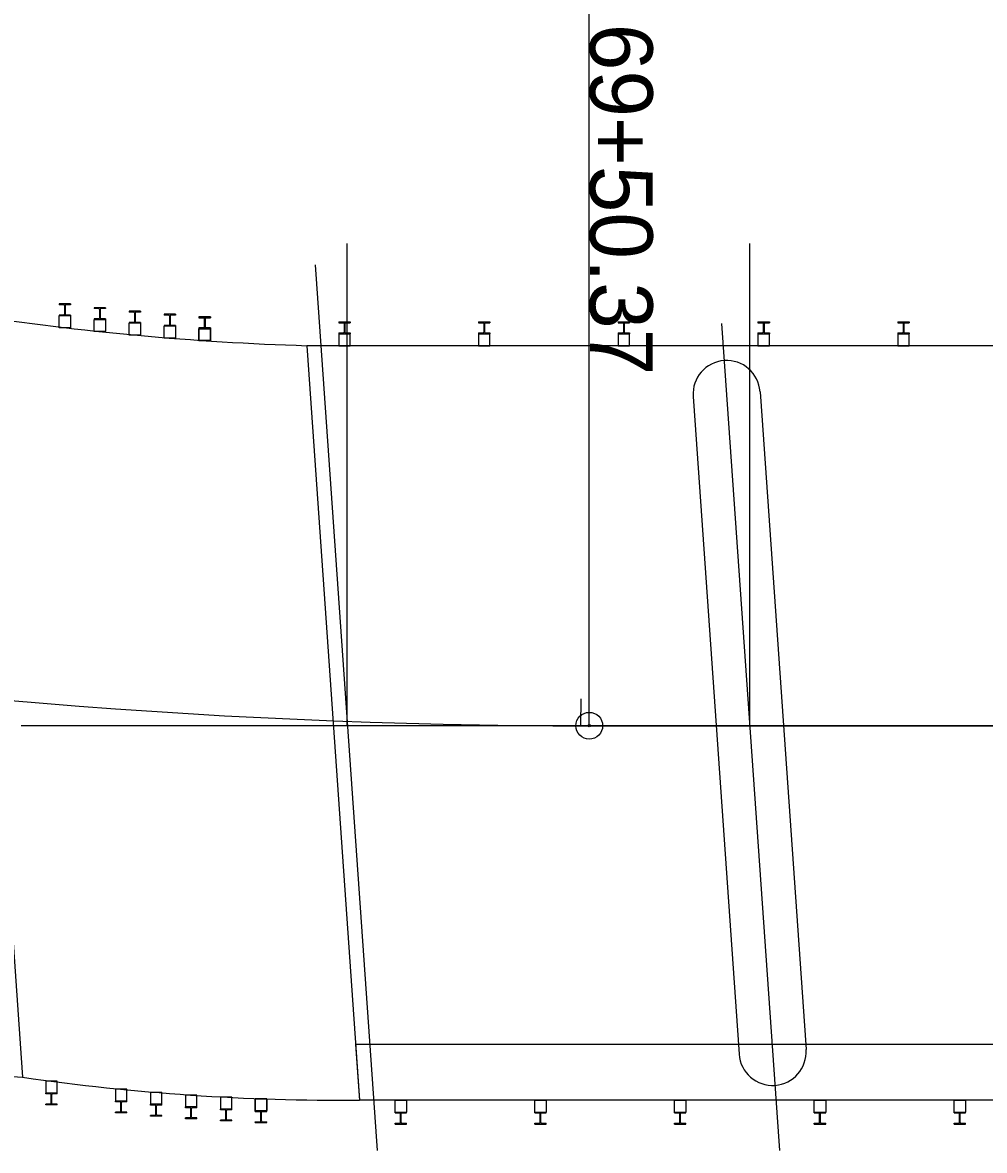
# Model space of a CAD drawing. Extents: x 27625 to 127752, y 6088 to 302357.
# Drawn here: x 27832.4 to 27875.5, y 6087.7 to 6138.1 of the extents above; entities that cross this region are included whole.
import ezdxf

# ---------------------------------------------------------------- set-up
doc = ezdxf.new("R2010")
doc.units = 0
for name, color, linetype in [('_CIVIL_CONSTRUCTION', 7, 'Continuous'), ('DR_X_Cells', 7, 'Continuous'), ('DV_X_Property_Line', 7, 'Continuous'), ('DV_X_Section_VMS_Line', 7, 'Continuous'), ('RS_Raster1', 7, 'Continuous'), ('RW_X_CL', 7, 'Continuous'), ('RW_X_CL_100_Bearings', 7, 'Continuous'), ('RW_X_CL_100_Cardinal_Points', 7, 'Continuous'), ('RW_X_CL_100_Curve_Data', 7, 'Continuous'), ('RW_X_CL_100_Stations', 7, 'Continuous'), ('RW_X_Fee_RW', 7, 'Continuous'), ('SC_Scratch2', 7, 'Continuous'), ('SV_X_Mon_Cells_Found', 7, 'Continuous'), ('SV_X_Shot_Marker', 7, 'Continuous'), ('TopoDOT_Transients', 7, 'Continuous')]:
    doc.layers.add(name, color=color, linetype=linetype)

msp = doc.modelspace()

# ---------------------------------------------------------------- linework, layer by layer
at = {"layer": '_CIVIL_CONSTRUCTION'}
for p, q in [((27846.96, 6106.658), (27846.96, 6128.23)), ((27864.96, 6106.658), (27864.96, 6128.23))]:
    msp.add_line(p, q, dxfattribs=at)
at = {"layer": 'DR_X_Cells'}
msp.add_line((27857.411, 6106.658), (27857.412, 6107.858), dxfattribs=at)
msp.add_line((27857.411, 6106.658), (27857.412, 6107.858), dxfattribs=at)
at = {"layer": 'DV_X_Property_Line'}
for p, q in [((27904.895, 6123.658), (27845.148, 6123.658)), ((27907.255, 6089.908), (27847.508, 6089.908))]:
    msp.add_line(p, q, dxfattribs=at)
at = {"layer": 'DV_X_Section_VMS_Line'}
msp.add_line((27905.46, 6106.658), (27832.372, 6106.658), dxfattribs=at)
at = {"layer": 'RS_Raster1'}
msp.add_circle((27857.78, 6106.658), 0.05, dxfattribs=at)
msp.add_circle((27857.78, 6106.658), 0.05, dxfattribs=at)
at = {"layer": 'RW_X_CL'}
for p, q in [((27862.426, 6121.39), (27864.484, 6091.966)), ((27865.419, 6121.6), (27867.477, 6092.176))]:
    msp.add_line(p, q, dxfattribs=at)
for centre, start, end in [((27863.923, 6121.495), 4, 184), ((27865.98, 6092.071), 184, 4)]:
    msp.add_arc(centre, 1.5, start, end, dxfattribs=at)
at = {"layer": 'RW_X_CL_100_Bearings'}
for p, q in [((27830.051, 6125.043), (27832.436, 6090.939)), ((27845.148, 6123.658), (27847.508, 6089.908))]:
    msp.add_line(p, q, dxfattribs=at)
for centre, radius, start, end in [((27849.042, 6249.077), 125.479, 261.29504, 268.22168), ((27846.864, 6191.18), 101.274, 261.80938, 270.36429)]:
    msp.add_arc(centre, radius, start, end, dxfattribs=at)
at = {"layer": 'RW_X_CL_100_Cardinal_Points'}
msp.add_line((27834.331, 6125.451), (27834.331, 6125.451), dxfattribs=at)
msp.add_arc((27857.78, 6401.934), 312.026, 262.69406, 265.34103, dxfattribs=at)
at = {"layer": 'RW_X_CL_100_Curve_Data'}
for p, q in [((27834.586, 6125.525), (27834.075, 6125.525)), ((27834.075, 6125.525), (27834.075, 6125.489)), ((27834.284, 6125.489), (27834.075, 6125.489)), ((27834.315, 6125.458), (27834.315, 6125.062)), ((27834.346, 6125.458), (27834.346, 6125.062)), ((27834.586, 6125.489), (27834.377, 6125.489)), ((27834.586, 6125.525), (27834.586, 6125.489)), ((27836.148, 6125.351), (27835.638, 6125.351)), ((27835.638, 6125.351), (27835.638, 6125.314)), ((27835.846, 6125.314), (27835.638, 6125.314)), ((27835.877, 6125.283), (27835.877, 6124.887)), ((27835.909, 6125.283), (27835.909, 6124.887)), ((27836.148, 6125.314), (27835.94, 6125.314)), ((27836.148, 6125.351), (27836.148, 6125.314)), ((27837.711, 6125.196), (27837.2, 6125.196)), ((27837.2, 6125.196), (27837.2, 6125.16)), ((27837.711, 6125.196), (27837.711, 6125.16)), ((27834.075, 6125.03), (27834.075, 6124.994)), ((27834.284, 6125.03), (27834.075, 6125.03)), ((27834.586, 6124.994), (27834.075, 6124.994)), ((27834.075, 6124.463), (27834.075, 6124.994)), ((27834.586, 6125.03), (27834.377, 6125.03)), ((27834.586, 6125.03), (27834.586, 6124.994)), ((27834.586, 6124.994), (27834.586, 6124.463)), ((27835.638, 6124.856), (27835.638, 6124.82)), ((27835.846, 6124.856), (27835.638, 6124.856)), ((27836.148, 6124.82), (27835.638, 6124.82)), ((27835.638, 6124.288), (27835.638, 6124.82)), ((27836.148, 6124.856), (27835.94, 6124.856)), ((27836.148, 6124.856), (27836.148, 6124.82)), ((27836.148, 6124.82), (27836.148, 6124.288)), ((27837.409, 6125.16), (27837.2, 6125.16)), ((27837.2, 6124.701), (27837.2, 6124.665)), ((27837.409, 6124.701), (27837.2, 6124.701)), ((27837.44, 6125.128), (27837.44, 6124.732)), ((27837.471, 6125.128), (27837.471, 6124.732)), ((27837.711, 6125.16), (27837.502, 6125.16)), ((27837.711, 6124.701), (27837.502, 6124.701)), ((27837.711, 6124.701), (27837.711, 6124.665)), ((27839.273, 6125.061), (27838.763, 6125.061)), ((27838.763, 6125.061), (27838.763, 6125.024)), ((27838.971, 6125.024), (27838.763, 6125.024)), ((27839.002, 6124.993), (27839.002, 6124.597)), ((27839.034, 6124.993), (27839.034, 6124.597)), ((27839.273, 6125.024), (27839.065, 6125.024)), ((27839.273, 6125.061), (27839.273, 6125.024)), ((27840.325, 6124.945), (27840.836, 6124.945)), ((27840.325, 6124.945), (27840.325, 6124.909)), ((27840.836, 6124.945), (27840.325, 6124.945)), ((27840.325, 6124.945), (27840.325, 6124.909)), ((27840.325, 6124.909), (27840.534, 6124.909)), ((27840.534, 6124.909), (27840.325, 6124.909)), ((27840.565, 6124.878), (27840.565, 6124.482)), ((27840.565, 6124.878), (27840.565, 6124.482)), ((27840.596, 6124.878), (27840.596, 6124.482)), ((27840.596, 6124.878), (27840.596, 6124.482)), ((27840.627, 6124.909), (27840.836, 6124.909)), ((27840.836, 6124.909), (27840.627, 6124.909)), ((27840.836, 6124.945), (27840.836, 6124.909)), ((27840.836, 6124.945), (27840.836, 6124.909)), ((27846.575, 6124.72), (27847.086, 6124.72)), ((27846.575, 6124.72), (27846.575, 6124.684)), ((27846.575, 6124.684), (27846.784, 6124.684)), ((27846.877, 6124.684), (27847.086, 6124.684)), ((27847.086, 6124.72), (27847.086, 6124.684)), ((27852.825, 6124.72), (27853.336, 6124.72)), ((27852.825, 6124.72), (27852.825, 6124.684)), ((27852.825, 6124.684), (27853.034, 6124.684)), ((27853.127, 6124.684), (27853.336, 6124.684)), ((27853.336, 6124.72), (27853.336, 6124.684)), ((27859.075, 6124.72), (27859.586, 6124.72)), ((27859.075, 6124.72), (27859.075, 6124.684)), ((27859.075, 6124.684), (27859.284, 6124.684)), ((27859.377, 6124.684), (27859.586, 6124.684)), ((27859.586, 6124.72), (27859.586, 6124.684)), ((27865.325, 6124.72), (27865.836, 6124.72)), ((27865.325, 6124.72), (27865.325, 6124.684)), ((27865.325, 6124.684), (27865.534, 6124.684)), ((27865.627, 6124.684), (27865.836, 6124.684)), ((27865.836, 6124.72), (27865.836, 6124.684)), ((27871.575, 6124.72), (27872.086, 6124.72)), ((27871.575, 6124.72), (27871.575, 6124.684)), ((27871.575, 6124.684), (27871.784, 6124.684)), ((27871.877, 6124.684), (27872.086, 6124.684)), ((27872.086, 6124.72), (27872.086, 6124.684)), ((27837.711, 6124.665), (27837.2, 6124.665)), ((27837.2, 6124.134), (27837.2, 6124.665)), ((27837.711, 6124.665), (27837.711, 6124.134)), ((27838.763, 6124.566), (27838.763, 6124.53)), ((27838.971, 6124.566), (27838.763, 6124.566)), ((27839.273, 6124.53), (27838.763, 6124.53)), ((27838.763, 6123.999), (27838.763, 6124.53)), ((27839.273, 6124.566), (27839.065, 6124.566)), ((27839.273, 6124.566), (27839.273, 6124.53)), ((27839.273, 6124.53), (27839.273, 6123.999)), ((27840.325, 6124.451), (27840.325, 6124.414)), ((27840.325, 6124.451), (27840.534, 6124.451)), ((27840.325, 6124.451), (27840.325, 6124.414)), ((27840.534, 6124.451), (27840.325, 6124.451)), ((27840.325, 6124.414), (27840.836, 6124.414)), ((27840.325, 6124.414), (27840.325, 6123.883)), ((27840.836, 6124.414), (27840.325, 6124.414)), ((27840.325, 6123.883), (27840.325, 6124.414)), ((27840.627, 6124.451), (27840.836, 6124.451)), ((27840.836, 6124.451), (27840.627, 6124.451)), ((27840.836, 6124.451), (27840.836, 6124.414)), ((27840.836, 6124.451), (27840.836, 6124.414)), ((27840.836, 6123.883), (27840.836, 6124.414)), ((27840.836, 6124.414), (27840.836, 6123.883)), ((27846.575, 6124.226), (27846.575, 6124.189)), ((27846.575, 6124.226), (27846.784, 6124.226)), ((27846.575, 6124.189), (27847.086, 6124.189)), ((27846.575, 6124.189), (27846.575, 6123.658)), ((27846.815, 6124.653), (27846.815, 6124.257)), ((27846.846, 6124.653), (27846.846, 6124.257)), ((27846.877, 6124.226), (27847.086, 6124.226)), ((27847.086, 6124.226), (27847.086, 6124.189)), ((27847.086, 6123.658), (27847.086, 6124.189)), ((27852.825, 6124.226), (27852.825, 6124.189)), ((27852.825, 6124.226), (27853.034, 6124.226)), ((27852.825, 6124.189), (27853.336, 6124.189)), ((27852.825, 6124.189), (27852.825, 6123.658)), ((27853.065, 6124.653), (27853.065, 6124.257)), ((27853.096, 6124.653), (27853.096, 6124.257)), ((27853.127, 6124.226), (27853.336, 6124.226)), ((27853.336, 6124.226), (27853.336, 6124.189)), ((27853.336, 6123.658), (27853.336, 6124.189)), ((27859.075, 6124.226), (27859.075, 6124.189)), ((27859.075, 6124.226), (27859.284, 6124.226)), ((27859.075, 6124.189), (27859.586, 6124.189)), ((27859.075, 6124.189), (27859.075, 6123.658)), ((27859.315, 6124.653), (27859.315, 6124.257)), ((27859.346, 6124.653), (27859.346, 6124.257)), ((27859.377, 6124.226), (27859.586, 6124.226)), ((27859.586, 6124.226), (27859.586, 6124.189)), ((27859.586, 6123.658), (27859.586, 6124.189)), ((27865.325, 6124.226), (27865.325, 6124.189)), ((27865.325, 6124.226), (27865.534, 6124.226)), ((27865.325, 6124.189), (27865.836, 6124.189)), ((27865.325, 6124.189), (27865.325, 6123.658)), ((27865.565, 6124.653), (27865.565, 6124.257)), ((27865.596, 6124.653), (27865.596, 6124.257)), ((27865.627, 6124.226), (27865.836, 6124.226)), ((27865.836, 6124.226), (27865.836, 6124.189)), ((27865.836, 6123.658), (27865.836, 6124.189)), ((27871.575, 6124.226), (27871.575, 6124.189)), ((27871.575, 6124.226), (27871.784, 6124.226)), ((27871.575, 6124.189), (27872.086, 6124.189)), ((27871.575, 6124.189), (27871.575, 6123.658)), ((27871.815, 6124.653), (27871.815, 6124.257)), ((27871.846, 6124.653), (27871.846, 6124.257)), ((27871.877, 6124.226), (27872.086, 6124.226)), ((27872.086, 6124.226), (27872.086, 6124.189)), ((27872.086, 6123.658), (27872.086, 6124.189)), ((27833.47, 6090.762), (27833.47, 6090.231)), ((27833.981, 6090.231), (27833.981, 6090.762)), ((27836.595, 6090.402), (27836.595, 6089.871)), ((27837.106, 6089.871), (27837.106, 6090.402)), ((27833.981, 6090.231), (27833.47, 6090.231)), ((27833.47, 6090.194), (27833.47, 6090.231)), ((27833.679, 6090.194), (27833.47, 6090.194)), ((27833.71, 6089.767), (27833.71, 6090.163)), ((27833.741, 6089.767), (27833.741, 6090.163)), ((27833.981, 6090.194), (27833.772, 6090.194)), ((27833.981, 6090.194), (27833.981, 6090.231)), ((27837.106, 6089.871), (27836.595, 6089.871)), ((27836.595, 6089.835), (27836.595, 6089.871)), ((27837.106, 6089.835), (27837.106, 6089.871)), ((27838.158, 6090.259), (27838.158, 6089.728)), ((27838.668, 6089.728), (27838.668, 6090.259)), ((27839.72, 6090.14), (27839.72, 6089.609)), ((27840.231, 6089.609), (27840.231, 6090.14)), ((27841.283, 6090.046), (27841.283, 6089.515)), ((27841.793, 6089.515), (27841.793, 6090.046)), ((27842.845, 6089.445), (27842.845, 6089.976)), ((27842.845, 6089.976), (27842.845, 6089.445)), ((27843.356, 6089.976), (27843.356, 6089.445)), ((27843.356, 6089.445), (27843.356, 6089.976)), ((27849.095, 6089.377), (27849.095, 6089.908)), ((27849.606, 6089.908), (27849.606, 6089.377)), ((27855.345, 6089.377), (27855.345, 6089.908)), ((27855.856, 6089.908), (27855.856, 6089.377)), ((27861.595, 6089.377), (27861.595, 6089.908)), ((27862.106, 6089.908), (27862.106, 6089.377)), ((27867.845, 6089.377), (27867.845, 6089.908)), ((27868.356, 6089.908), (27868.356, 6089.377)), ((27874.095, 6089.377), (27874.095, 6089.908)), ((27874.606, 6089.908), (27874.606, 6089.377)), ((27833.47, 6089.699), (27833.47, 6089.736)), ((27833.679, 6089.736), (27833.47, 6089.736)), ((27833.981, 6089.699), (27833.47, 6089.699)), ((27833.981, 6089.736), (27833.772, 6089.736)), ((27833.981, 6089.699), (27833.981, 6089.736)), ((27836.804, 6089.835), (27836.595, 6089.835)), ((27836.595, 6089.34), (27836.595, 6089.376)), ((27836.804, 6089.376), (27836.595, 6089.376)), ((27836.835, 6089.407), (27836.835, 6089.803)), ((27836.866, 6089.407), (27836.866, 6089.803)), ((27837.106, 6089.835), (27836.897, 6089.835)), ((27837.106, 6089.376), (27836.897, 6089.376)), ((27837.106, 6089.34), (27837.106, 6089.376)), ((27838.668, 6089.728), (27838.158, 6089.728)), ((27838.158, 6089.692), (27838.158, 6089.728)), ((27838.366, 6089.692), (27838.158, 6089.692)), ((27838.397, 6089.264), (27838.397, 6089.66)), ((27838.429, 6089.264), (27838.429, 6089.66)), ((27838.668, 6089.692), (27838.46, 6089.692)), ((27838.668, 6089.692), (27838.668, 6089.728)), ((27840.231, 6089.609), (27839.72, 6089.609)), ((27839.72, 6089.573), (27839.72, 6089.609)), ((27839.929, 6089.573), (27839.72, 6089.573)), ((27839.96, 6089.146), (27839.96, 6089.542)), ((27839.991, 6089.146), (27839.991, 6089.542)), ((27840.231, 6089.573), (27840.022, 6089.573)), ((27840.231, 6089.573), (27840.231, 6089.609)), ((27841.793, 6089.515), (27841.283, 6089.515)), ((27841.283, 6089.478), (27841.283, 6089.515)), ((27841.491, 6089.478), (27841.283, 6089.478)), ((27841.522, 6089.051), (27841.522, 6089.447)), ((27841.554, 6089.051), (27841.554, 6089.447)), ((27841.793, 6089.478), (27841.585, 6089.478)), ((27841.793, 6089.478), (27841.793, 6089.515)), ((27842.845, 6089.445), (27843.356, 6089.445)), ((27842.845, 6089.408), (27842.845, 6089.445)), ((27842.845, 6089.408), (27843.054, 6089.408)), ((27843.085, 6088.981), (27843.085, 6089.377)), ((27843.116, 6088.981), (27843.116, 6089.377)), ((27843.147, 6089.408), (27843.356, 6089.408)), ((27843.356, 6089.408), (27843.356, 6089.445)), ((27849.095, 6089.377), (27849.606, 6089.377)), ((27849.095, 6089.34), (27849.095, 6089.377)), ((27849.606, 6089.34), (27849.606, 6089.377)), ((27855.345, 6089.377), (27855.856, 6089.377)), ((27855.345, 6089.34), (27855.345, 6089.377)), ((27855.856, 6089.34), (27855.856, 6089.377)), ((27861.595, 6089.377), (27862.106, 6089.377)), ((27861.595, 6089.34), (27861.595, 6089.377)), ((27862.106, 6089.34), (27862.106, 6089.377)), ((27867.845, 6089.377), (27868.356, 6089.377)), ((27867.845, 6089.34), (27867.845, 6089.377)), ((27868.356, 6089.34), (27868.356, 6089.377)), ((27874.095, 6089.377), (27874.606, 6089.377)), ((27874.095, 6089.34), (27874.095, 6089.377)), ((27874.606, 6089.34), (27874.606, 6089.377)), ((27837.106, 6089.34), (27836.595, 6089.34)), ((27838.158, 6089.197), (27838.158, 6089.233)), ((27838.366, 6089.233), (27838.158, 6089.233)), ((27838.668, 6089.197), (27838.158, 6089.197)), ((27838.668, 6089.233), (27838.46, 6089.233)), ((27838.668, 6089.197), (27838.668, 6089.233)), ((27839.72, 6089.078), (27839.72, 6089.115)), ((27839.929, 6089.115), (27839.72, 6089.115)), ((27840.231, 6089.078), (27839.72, 6089.078)), ((27840.231, 6089.115), (27840.022, 6089.115)), ((27840.231, 6089.078), (27840.231, 6089.115)), ((27841.283, 6088.984), (27841.283, 6089.02)), ((27841.491, 6089.02), (27841.283, 6089.02)), ((27841.793, 6088.984), (27841.283, 6088.984)), ((27841.793, 6089.02), (27841.585, 6089.02)), ((27841.793, 6088.984), (27841.793, 6089.02)), ((27842.845, 6088.914), (27842.845, 6088.95)), ((27842.845, 6088.95), (27843.054, 6088.95)), ((27842.845, 6088.914), (27843.356, 6088.914)), ((27843.147, 6088.95), (27843.356, 6088.95)), ((27843.356, 6088.914), (27843.356, 6088.95)), ((27849.095, 6089.34), (27849.304, 6089.34)), ((27849.095, 6088.846), (27849.095, 6088.882)), ((27849.095, 6088.882), (27849.304, 6088.882)), ((27849.335, 6088.913), (27849.335, 6089.309)), ((27849.366, 6088.913), (27849.366, 6089.309)), ((27849.397, 6089.34), (27849.606, 6089.34)), ((27849.397, 6088.882), (27849.606, 6088.882)), ((27849.606, 6088.846), (27849.606, 6088.882)), ((27855.345, 6089.34), (27855.554, 6089.34)), ((27855.345, 6088.846), (27855.345, 6088.882)), ((27855.345, 6088.882), (27855.554, 6088.882)), ((27855.585, 6088.913), (27855.585, 6089.309)), ((27855.616, 6088.913), (27855.616, 6089.309)), ((27855.647, 6089.34), (27855.856, 6089.34)), ((27855.647, 6088.882), (27855.856, 6088.882)), ((27855.856, 6088.846), (27855.856, 6088.882)), ((27861.595, 6089.34), (27861.804, 6089.34)), ((27861.595, 6088.846), (27861.595, 6088.882)), ((27861.595, 6088.882), (27861.804, 6088.882)), ((27861.835, 6088.913), (27861.835, 6089.309)), ((27861.866, 6088.913), (27861.866, 6089.309)), ((27861.897, 6089.34), (27862.106, 6089.34)), ((27861.897, 6088.882), (27862.106, 6088.882)), ((27862.106, 6088.846), (27862.106, 6088.882)), ((27867.845, 6089.34), (27868.054, 6089.34)), ((27867.845, 6088.846), (27867.845, 6088.882)), ((27867.845, 6088.882), (27868.054, 6088.882)), ((27868.085, 6088.913), (27868.085, 6089.309)), ((27868.116, 6088.913), (27868.116, 6089.309)), ((27868.147, 6089.34), (27868.356, 6089.34)), ((27868.147, 6088.882), (27868.356, 6088.882)), ((27868.356, 6088.846), (27868.356, 6088.882)), ((27874.095, 6089.34), (27874.304, 6089.34)), ((27874.095, 6088.846), (27874.095, 6088.882)), ((27874.095, 6088.882), (27874.304, 6088.882)), ((27874.335, 6088.913), (27874.335, 6089.309)), ((27874.366, 6088.913), (27874.366, 6089.309)), ((27874.397, 6089.34), (27874.606, 6089.34)), ((27874.397, 6088.882), (27874.606, 6088.882)), ((27874.606, 6088.846), (27874.606, 6088.882)), ((27849.095, 6088.846), (27849.606, 6088.846)), ((27855.345, 6088.846), (27855.856, 6088.846)), ((27861.595, 6088.846), (27862.106, 6088.846)), ((27867.845, 6088.846), (27868.356, 6088.846)), ((27874.095, 6088.846), (27874.606, 6088.846))]:
    msp.add_line(p, q, dxfattribs=at)
for centre, start, end in [((27834.284, 6125.458), 0, 90), ((27834.377, 6125.458), 90, 180), ((27835.846, 6125.283), 0, 90), ((27835.94, 6125.283), 90, 180), ((27834.284, 6125.062), 270, 0), ((27834.377, 6125.062), 180, 270), ((27835.846, 6124.887), 270, 0), ((27835.94, 6124.887), 180, 270), ((27837.409, 6125.128), 0, 90), ((27837.409, 6124.732), 270, 0), ((27837.502, 6125.128), 90, 180), ((27837.502, 6124.732), 180, 270), ((27838.971, 6124.993), 0, 90), ((27839.065, 6124.993), 90, 180), ((27840.534, 6124.878), 0, 90), ((27840.534, 6124.878), 0, 90), ((27840.628, 6124.878), 90, 180), ((27840.627, 6124.878), 90, 180), ((27846.784, 6124.653), 0, 90), ((27846.878, 6124.653), 90, 180), ((27853.034, 6124.653), 0, 90), ((27853.128, 6124.653), 90, 180), ((27859.284, 6124.653), 0, 90), ((27859.378, 6124.653), 90, 180), ((27865.534, 6124.653), 0, 90), ((27865.628, 6124.653), 90, 180), ((27871.784, 6124.653), 0, 90), ((27871.878, 6124.653), 90, 180), ((27838.971, 6124.597), 270, 0), ((27839.065, 6124.597), 180, 270), ((27840.534, 6124.482), 270, 0), ((27840.534, 6124.482), 270, 0), ((27840.628, 6124.482), 180, 270), ((27840.627, 6124.482), 180, 270), ((27846.784, 6124.257), 270, 0), ((27846.878, 6124.257), 180, 270), ((27853.034, 6124.257), 270, 0), ((27853.128, 6124.257), 180, 270), ((27859.284, 6124.257), 270, 0), ((27859.378, 6124.257), 180, 270), ((27865.534, 6124.257), 270, 0), ((27865.628, 6124.257), 180, 270), ((27871.784, 6124.257), 270, 0), ((27871.878, 6124.257), 180, 270), ((27833.679, 6090.163), 360, 90), ((27833.772, 6090.163), 90, 180), ((27833.679, 6089.767), 270, 360), ((27833.772, 6089.767), 180, 270), ((27836.804, 6089.803), 360, 90), ((27836.804, 6089.408), 270, 360), ((27836.897, 6089.803), 90, 180), ((27836.897, 6089.408), 180, 270), ((27838.366, 6089.66), 360, 90), ((27838.46, 6089.66), 90, 180), ((27839.929, 6089.542), 360, 90), ((27840.022, 6089.542), 90, 180), ((27841.491, 6089.447), 360, 90), ((27841.585, 6089.447), 90, 180), ((27843.054, 6089.377), 0, 90), ((27843.148, 6089.377), 90, 180), ((27838.366, 6089.264), 270, 360), ((27838.46, 6089.264), 180, 270), ((27839.929, 6089.146), 270, 360), ((27840.022, 6089.146), 180, 270), ((27841.491, 6089.051), 270, 360), ((27841.585, 6089.051), 180, 270), ((27843.054, 6088.981), 270, 0), ((27843.148, 6088.981), 180, 270), ((27849.304, 6089.309), 0, 90), ((27849.304, 6088.913), 270, 0), ((27849.398, 6089.309), 90, 180), ((27849.398, 6088.913), 180, 270), ((27855.554, 6089.309), 0, 90), ((27855.554, 6088.913), 270, 0), ((27855.648, 6089.309), 90, 180), ((27855.648, 6088.913), 180, 270), ((27861.804, 6089.309), 0, 90), ((27861.804, 6088.913), 270, 0), ((27861.898, 6089.309), 90, 180), ((27861.898, 6088.913), 180, 270), ((27868.054, 6089.309), 0, 90), ((27868.054, 6088.913), 270, 0), ((27868.148, 6089.309), 90, 180), ((27868.148, 6088.913), 180, 270), ((27874.304, 6089.309), 0, 90), ((27874.304, 6088.913), 270, 0), ((27874.398, 6089.309), 90, 180), ((27874.398, 6088.913), 180, 270)]:
    msp.add_arc(centre, 0.0312, start, end, dxfattribs=at)
at = {"layer": 'RW_X_CL_100_Stations'}
for p, q in [((27834.586, 6124.463), (27834.075, 6124.463)), ((27836.148, 6124.288), (27835.638, 6124.288)), ((27837.711, 6124.134), (27837.2, 6124.134)), ((27839.273, 6123.999), (27838.763, 6123.999)), ((27840.325, 6123.883), (27840.836, 6123.883)), ((27840.836, 6123.883), (27840.325, 6123.883)), ((27846.575, 6123.658), (27847.086, 6123.658)), ((27852.825, 6123.658), (27853.336, 6123.658)), ((27859.075, 6123.658), (27859.586, 6123.658)), ((27865.325, 6123.658), (27865.836, 6123.658)), ((27871.575, 6123.658), (27872.086, 6123.658)), ((27833.981, 6090.762), (27833.47, 6090.762)), ((27837.106, 6090.402), (27836.595, 6090.402)), ((27838.668, 6090.259), (27838.158, 6090.259)), ((27840.231, 6090.14), (27839.72, 6090.14)), ((27841.793, 6090.046), (27841.283, 6090.046)), ((27842.845, 6089.976), (27843.356, 6089.976)), ((27843.356, 6089.976), (27842.845, 6089.976)), ((27849.095, 6089.908), (27849.606, 6089.908)), ((27855.345, 6089.908), (27855.856, 6089.908)), ((27861.595, 6089.908), (27862.106, 6089.908)), ((27867.845, 6089.908), (27868.356, 6089.908)), ((27874.095, 6089.908), (27874.606, 6089.908))]:
    msp.add_line(p, q, dxfattribs=at)
at = {"layer": 'RW_X_Fee_RW'}
for p, q in [((27845.519, 6127.27), (27848.288, 6087.664)), ((27863.702, 6124.655), (27866.288, 6087.664))]:
    msp.add_line(p, q, dxfattribs=at)
at = {"layer": 'SC_Scratch2'}
msp.add_line((27857.78, 6106.658), (27857.78, 6128.23), dxfattribs=at)
msp.add_line((27857.78, 6106.658), (27857.78, 6128.23), dxfattribs=at)
at = {"layer": 'SV_X_Mon_Cells_Found'}
msp.add_line((27857.78, 6106.658), (27857.78, 6151.658), dxfattribs=at)
msp.add_circle((27857.78, 6106.658), 0.6, dxfattribs=at)
at = {"layer": 'SV_X_Shot_Marker'}
msp.add_line((27857.78, 6106.658), (28207.41, 6106.658), dxfattribs=at)
msp.add_arc((27857.78, 6401.934), 295.276, 229.785, 270, dxfattribs=at)
msp.add_arc((27857.78, 6401.934), 295.276, 229.785, 270, dxfattribs=at)
at = {"layer": 'TopoDOT_Transients'}
for p, q in [((27907.08, 6092.408), (27847.333, 6092.408)), ((27847.333, 6092.408), (27847.508, 6089.908)), ((27907.255, 6089.908), (27847.508, 6089.908))]:
    msp.add_line(p, q, dxfattribs=at)

# ---------------------------------------------------------------- texts
at = {"layer": 'SV_X_Mon_Cells_Found'}
msp.add_text('69+50.37', height=2.8, rotation=270, dxfattribs=at).set_placement((27857.817, 6138.054))

doc.saveas('drawing.dxf')
